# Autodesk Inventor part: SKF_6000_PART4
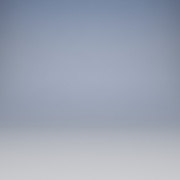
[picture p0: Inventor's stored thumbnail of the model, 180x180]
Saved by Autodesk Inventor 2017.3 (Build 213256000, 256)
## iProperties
Part Number: SKF_6000_PART4
Material: Generic
Catalog Web Link: www.cadenas.de
Description: -Deep groove ball bearings
Vendor: SKF
Document SubType Name: Modeling
Designer: partserver
Manufacturer: SKF
Mass: 19 g
Density: 1 g/cm^3
Appearance: PSOLRGB-192-192-192
Category: PARTsolutions
Company: SKF
Title: SKF_6000_PART4
Author: Cadenas PARTsolutions
Comments: Deep groove ball bearings
PSOL_IDENT_0: {$CADENAS_DATA\23d-libs\skf\bearings_units_and_housings\ball_bearings\deep_groove_ball_bearings\bb1_
PSOL_IDENT_1: 001_101.prj},194 {VTYP=3D},{NB=SKF_6000_PART4},{LINA=SKF_6000_PART4},{NN=BB1_001_101_PART4},{NOPRJ=T
PSOL_IDENT_2: RUE},{DATE=18.06.2021 07:30:58},{GEOMDATE=16.06.2021 12:48:44},{VERSION=},{LINEID=5840},{WBVAR=},{WB
PSOL_IDENT_3: NUMERIC=}  {NB=SKF_6000_PART4},{LINA=SKF_6000_PART4},{KT=DUMMY},{DESIGNATION=6000},{R12=0.30},{DD=10
PSOL_IDENT_4: .000},{D=26.000},{B=8.000},{C=},{CX=},{CXX=},{CA=0.000},{XXVARIANT=},{XXDESIGN=Single row},{XXSEALIN
PSOL_IDENT_5: G=No seals},{DESIGN=dgbb1},{DESIGNIR=dgbb1},{VARIANT=},{DD1=14.80},{DD2=},{DD2X=},{DD2A=0.00},{D1=21
PSOL_IDENT_6: .20},{D1X=MIN},{D2=22.6},{D2A=22.60},{D3=},{D3X=},{D3A=0.000},{D4=},{HH=MIN},{BB=MIN},{BBX=},{BBA=0.
PSOL_IDENT_7: 000},{FF=},{R0MAX=MIN},{R0=MIN},{PITCH=17.80},{DW=4.762},{DDAMIN=12.000},{DDAMAX=MIN},{DDBMIN=MIN},{
PSOL_IDENT_8: DDBMAX=MIN},{DBMIN=MIN},{DAMAX=24.000},{BBAMIN=MIN},{CAMAX=MIN},{RAMAX=0.300},{LOAD1=4.750},{LOAD2=1
PSOL_IDENT_9: .960},{LOAD3=0.083},{SPEED1=67000},{SPEED2=40000},{KR=0.025},{F0=12.000},{Z=7},{II=1},{MASS=0.019},{
PSOL_IDENT_10: BEARING=6000},{RING=},{HELP=2.400},{HELP2=1.700},{DD1ALG=7.400},{YALG=7.400},{PITCH1=17.800},{DW1=4.
PSOL_IDENT_11: 762},{YALG1=10.600},{HALG1=2.400},{SH=7.400},{CU=0.648},{HALG=2.4},{B1=0},{SHIELDHELP=1},{D4A=0.000}
PSOL_IDENT_12: ,{FFA=0.000},{RS1=}
NB: SKF_6000_PART4
NT: Deep groove ball bearings
NBSYN: SKF_$DESIGNATION._PART4
LINA: SKF_6000_PART4
CATALOG: SKF
DESIGNATION: 6000
R12: 0.3
DD: 10
D: 26
B: 8
D2: 22.6
LOAD1: 4.75
LOAD2: 1.96
LOAD3: 0.083
SPEED1: 67000
SPEED2: 40000
BEARING: 6000
SUPPLIER: SKF
ARTICLENO: SKF_6000_PART4
BOMINFO: SKF_6000_PART4
CREATOR: CADENAS GmbH
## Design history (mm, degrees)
node "no_geo_XY"
node "no_geo_YZ"
node "no_geo_ZX"
node "no_geo_X"
node "no_geo_Y"
node "no_geo_Z"
node "no_geo_Center"
